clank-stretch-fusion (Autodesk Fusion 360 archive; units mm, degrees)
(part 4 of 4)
sketch "Sketch41" plane through (0, 0, 0) normal (0, 0, 1) x axis (1, 0, 0)
  line L1 (-93, -22.24) -> (-35, -22.24)
  line L2 (-93, 7.76) -> (-93, -22.24)
  line L3 (-35, 7.76) -> (-93, 7.76)
  line L4 (-35, -22.24) -> (-35, 7.76)
  line L5 (-17.5, 20.25) -> (-17.5, -22.74)
  line L6 (-93.5, -22.74) -> (-17.5, -22.74)
  line L7 (-93.5, 8.26) -> (-93.5, -22.74)
  line L8 (-17.5, 8.26) -> (-93.5, 8.26)
  line L9 (-36, -1.24) -> (-36, 6.76)
  line L10 (-62.3606, -1.24) -> (-36, -1.24)
  line L11 (-62.3606, -11.24) -> (-62.3606, -1.24)
  line L12 (-36, -11.24) -> (-62.3606, -11.24)
  line L13 (-36, -21.24) -> (-36, -11.24)
  line L14 (-65.6394, -21.24) -> (-36, -21.24)
  line L15 (-65.6394, -11.24) -> (-65.6394, -21.24)
  line L16 (-92, -11.24) -> (-65.6394, -11.24)
  line L17 (-92, 6.76) -> (-92, -11.24)
  line L18 (-36, 6.76) -> (-92, 6.76)
  line L19 (-20, -36.7914) -> (-20, -46.6952)
  line L20 (-45, 9.76) -> (-83, 9.76)
  line L21 (-45, 10.76) -> (-45, 9.76)
  line L22 (-83, 10.76) -> (-45, 10.76)
  line L23 (-83, 9.76) -> (-83, 10.76)
  line L24 (-64, 9.76) -> (-64, 7.76)
  circle C1 centre (-39, -6.24) radius 1.35
  circle C2 centre (-89, -18.24) radius 1.35
  point P10 (-64, 7.76)
  point P6 (-17.5, -22.74)
  point P11 (-17.5, -22.74)
  point P14 (-17.5, 8.26)
  point P18 (-62.3606, -11.24)
  point P16 (-36, -1.24)
  point P32 (-64, 7.76)
  point P33 (-64, 9.76)
  point P2 (-35, -22.24)
  point P3 (-93, -22.24)
  point P4 (-93, 7.76)
  point P8 (-39, -6.24)
  point P9 (-89, -18.24)
  point P1 (0, 0)
  point P5 (-35, 7.76)
  point P27 (0, 0)
  point P28 (-83, 9.76)
  point P29 (-45, 9.76)
  point P31 (-83, 10.76)
  horizontal L1
  vertical L2
  horizontal L3
  vertical L4
  equal C1 C2
  coincident L3 P10
  midpoint L3 P10
  coincident P6 P11
  perpendicular L5 L6
  perpendicular L6 L7
  coincident L5 P14
  perpendicular L5 L8
  vertical L9
  perpendicular L9 L10
  perpendicular L10 L11
  perpendicular L11 L12
  perpendicular L12 L13
  perpendicular L13 L14
  perpendicular L14 L15
  perpendicular L15 L16
  perpendicular L16 L17
  horizontal L18
  coincident P18 L16
  equal L12 L16
  coincident P16 L13
  vertical L19
  horizontal L20
  vertical L21
  horizontal L22
  vertical L23
  coincident P10 P32
  midpoint L20 P33
  vertical L24
  dimension "d2447" distance P2 P3 = 58
  dimension "d2448" distance P3 P4 = 30
  dimension "d2449" distance L4 P8 = 4
  dimension "d2450" distance L1 P9 = 4
  dimension "d2451" distance L2 P9 = 4
  dimension "d2452" distance L3 P8 = 14
  dimension "d2453" diameter C1 = 2.7
  dimension "d2454" distance P1 P10 = 64
  dimension "d2455" distance L1 P6 = 0.5
  dimension "d2456" distance P5 L8 = 0.5
  dimension "d2457" distance P4 L7 = 0.5
  dimension "d2458" distance L3 L18 = 1
  dimension "d2459" distance L4 L9 = 1
  dimension "d2460" distance L1 L14 = 1
  dimension "d2461" distance L2 L17 = 1
  dimension "d2462" distance P8 L12 = 5
  dimension "d2463" distance P8 L10 = 5 (= "d2462")
  dimension "d2479" distance L19 P27 = 20
  dimension "d2480" distance P10 L19 = 44
  dimension "d2481" distance P28 P29 = 38
  dimension "d2482" distance P28 P31 = 1
  dimension "d2483" distance P32 P33 = 2
extrude "Extrude174" sketch "Sketch41" profile of L5 C1 C2 L6 L7 L8 L9 L10 L11 L12 L13 L14 L15 L16 L17 L18 to an object
extrude "Extrude175" sketch "Sketch41" profile of L9 L10 L11 L12 L13 L14 L15 L16 L17 L18 to an object offset -5
fillet "Fillet71" radius 2
fillet "Fillet72" radius 4
component_from_bodies "Body->Comp1"
component_from_bodies "Body->Comp2"
component_from_bodies "Body->Comp3"
component_from_bodies "Body->Comp4"
component_from_bodies "Body->Comp5"
component_from_bodies "Body->Comp6"
component_from_bodies "Body->Comp7"
as_built_joint "As-built1"
as_built_joint "As-built2"
as_built_joint "As-built3"
as_built_joint "As-built4"
as_built_joint "As-built5"
as_built_joint "As-built6"
as_built_joint "As-built7"
component_insert "Component Insert111"
joint "Assemble127" alignAngle 0 alignOffsetX 0 alignOffsetY 0 alignOffsetZ 0
component_insert "Component Insert112"
joint "Assemble128" alignAngle 0 alignOffsetX 0 alignOffsetY 0 alignOffsetZ 0
component_insert "Component Insert113"
joint "Assemble129" alignAngle 180 alignOffsetX 0 alignOffsetY 0 alignOffsetZ 0
component_insert "Component Insert114"
joint "Assemble130" alignAngle 180 alignOffsetX 0 alignOffsetY 0 alignOffsetZ 0
component_insert "Component Insert115"
joint "Assemble131" alignAngle 0 alignOffsetX 0 alignOffsetY 0 alignOffsetZ 0
component_insert "Component Insert116"
joint "Assemble132" alignAngle 0 alignOffsetX 0 alignOffsetY 0 alignOffsetZ 0
component_insert "Component Insert117"
joint "Assemble133" alignAngle 180 alignOffsetX 0 alignOffsetY 0 alignOffsetZ 0
component_insert "Component Insert118"
joint "Assemble134" alignAngle 180 alignOffsetX 0 alignOffsetY 0 alignOffsetZ 0
component_insert "Component Insert119"
joint "Assemble135" alignAngle -90 alignOffsetX 0 alignOffsetY 0 alignOffsetZ 0
component_insert "Component Insert120"
joint "Assemble119" alignAngle 0 alignOffsetX 0 alignOffsetY 0 alignOffsetZ -2.1
component_insert "Component Insert128"
joint "Assemble136" alignAngle -90 alignOffsetX 0 alignOffsetY 0 alignOffsetZ 0
component_insert "Component Insert129"
joint "Assemble137" alignAngle -90 alignOffsetX 0 alignOffsetY 0 alignOffsetZ 0
component_insert "Component Insert130"
joint "Assemble138" alignAngle -90 alignOffsetX 0 alignOffsetY 0 alignOffsetZ 0
component_insert "Component Insert121"
joint "Assemble139" alignAngle -180 alignOffsetX 0 alignOffsetY 0 alignOffsetZ 0
component_insert "Component Insert131"
joint "Assemble140" alignAngle 0 alignOffsetX 0 alignOffsetY 0 alignOffsetZ 0
component_insert "Component Insert132"
joint "Assemble141" alignAngle 0 alignOffsetX 0 alignOffsetY 0 alignOffsetZ 0
component_insert "Component Insert133"
joint "Assemble142" alignAngle 180 alignOffsetX 0 alignOffsetY 0 alignOffsetZ 0
component_insert "Component Insert134"
joint "Assemble143" alignAngle 180 alignOffsetX 0 alignOffsetY 0 alignOffsetZ 0
component_insert "Component Insert135"
joint "Assemble144" alignAngle 180 alignOffsetX 0 alignOffsetY 0 alignOffsetZ 0
component_insert "Component Insert136"
joint "Assemble145" alignAngle 180 alignOffsetX 0 alignOffsetY 0 alignOffsetZ 0
component_insert "Component Insert137"
joint "Assemble146" alignAngle 0 alignOffsetX 0 alignOffsetY 0 alignOffsetZ 0
component_insert "Component Insert138"
joint "Assemble147" alignAngle 30 alignOffsetX 0 alignOffsetY 0 alignOffsetZ 0
component_insert "Component Insert139"
joint "Assemble148" alignAngle 0 alignOffsetX 0 alignOffsetY 0 alignOffsetZ 0
component_insert "Component Insert140"
joint "Assemble149" alignAngle 30 alignOffsetX 0 alignOffsetY 0 alignOffsetZ -1.5
component_insert "Component Insert141"
joint "Assemble150" alignAngle 30 alignOffsetX 0 alignOffsetY 0 alignOffsetZ -1.5
component_insert "Component Insert142"
joint "Assemble151" alignAngle 30 alignOffsetX 0 alignOffsetY 0 alignOffsetZ -1.5
component_insert "Component Insert143"
joint "Assemble152" alignAngle 30 alignOffsetX 0 alignOffsetY 0 alignOffsetZ -1.5
component_insert "Component Insert144"
joint "Assemble153" alignAngle 30 alignOffsetX 0 alignOffsetY 0 alignOffsetZ -1.5
component_insert "Component Insert145"
joint "Assemble154" alignAngle 30 alignOffsetX 0 alignOffsetY 0 alignOffsetZ -1.5
component_insert "Component Insert146"
joint "Assemble155" alignAngle 30 alignOffsetX 0 alignOffsetY 0 alignOffsetZ -1.5
component_insert "Component Insert147"
joint "Assemble156" alignAngle 30 alignOffsetX 0 alignOffsetY 0 alignOffsetZ 0
component_insert "Component Insert148"
joint "Assemble157" alignAngle 0 alignOffsetX 0 alignOffsetY 0 alignOffsetZ 0
component_insert "Component Insert149"
joint "Assemble158" alignAngle 0 alignOffsetX 0 alignOffsetY 0 alignOffsetZ 0
component_insert "Component Insert150"
joint "Assemble159" alignAngle 0 alignOffsetX 0 alignOffsetY 0 alignOffsetZ 0
component_insert "Component Insert151"
joint "Assemble160" alignAngle 0 alignOffsetX 0 alignOffsetY 0 alignOffsetZ 0
component_insert "Component Insert152"
joint "Assemble161" alignAngle 0 alignOffsetX 0 alignOffsetY 0 alignOffsetZ 0
component_insert "Component Insert153"
joint "Assemble162" alignAngle 0 alignOffsetX 0 alignOffsetY 0 alignOffsetZ 0
component_insert "Component Insert154"
joint "Assemble163" alignAngle 0 alignOffsetX 0 alignOffsetY 0 alignOffsetZ 0
component_insert "Component Insert155"
joint "Assemble164" alignAngle 0 alignOffsetX 0 alignOffsetY 0 alignOffsetZ 0
component_insert "Component Insert156"
joint "Assemble165" alignAngle 0 alignOffsetX 0 alignOffsetY 0 alignOffsetZ 0
component_insert "Component Insert157"
joint "Assemble166" alignAngle 0 alignOffsetX 0 alignOffsetY 0 alignOffsetZ 0
component_insert "Component Insert158"
joint "Assemble167" alignAngle 0 alignOffsetX 0 alignOffsetY 0 alignOffsetZ 0
component_insert "Component Insert159"
joint "Assemble168" alignAngle 0 alignOffsetX 0 alignOffsetY 0 alignOffsetZ 0
component_insert "Component Insert160"
joint "Assemble169" alignAngle 0 alignOffsetX 0 alignOffsetY 0 alignOffsetZ 0
component_insert "Component Insert161"
joint "Assemble170" alignAngle 0 alignOffsetX 0 alignOffsetY 0 alignOffsetZ 0
component_insert "Component Insert162"
joint "Assemble171" alignAngle 0 alignOffsetX 0 alignOffsetY 0 alignOffsetZ 0
component_insert "Component Insert163"
joint "Assemble172" alignAngle 0 alignOffsetX 0 alignOffsetY 0 alignOffsetZ 0
component_insert "Component Insert164"
joint "Assemble173" alignAngle 0 alignOffsetX 0 alignOffsetY 0 alignOffsetZ 0
component_insert "Component Insert165"
joint "Assemble174" alignAngle 0 alignOffsetX 0 alignOffsetY 0 alignOffsetZ 0
component_insert "Component Insert166"
joint "Assemble175" alignAngle 0 alignOffsetX 0 alignOffsetY 0 alignOffsetZ 0
component_insert "Component Insert167"
joint "Assemble176" alignAngle 0 alignOffsetX 0 alignOffsetY 0 alignOffsetZ 0
component_insert "Component Insert168"
joint "Assemble177" alignAngle 0 alignOffsetX 0 alignOffsetY 0 alignOffsetZ -6
component_insert "Component Insert169"
joint "Assemble178" alignAngle 0 alignOffsetX 0 alignOffsetY 0 alignOffsetZ 0
component_insert "Component Insert171"
joint "Assemble180" alignAngle 180 alignOffsetX 0 alignOffsetY 0 alignOffsetZ 0
component_insert "Component Insert172"
joint "Assemble181" alignAngle 0 alignOffsetX 0 alignOffsetY 0 alignOffsetZ 0
component_insert "Component Insert173"
joint "Assemble182" alignAngle 0 alignOffsetX 0 alignOffsetY 0 alignOffsetZ 0
component_insert "Component Insert174"
joint "Assemble183" alignAngle 0 alignOffsetX 0 alignOffsetY 0 alignOffsetZ 0
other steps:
base_feature "Base Feature1" bodies "YL Side Plate"
base_feature "Base Feature1" bodies "YL Belt Clip Teeth"
base_feature "Base Feature1" bodies "YL Belt Clip Face"
base_feature "Base Feature1" bodies "YL Top Plate"
base_feature "Base Feature1" bodies "YL Idler Cap"
base_feature "Base Feature1" bodies "YL Motor Plate"
base_feature "Base Feature1" bodies "YL Cable Clip"
create_component "CreateComponent1"
remove_body "RemoveBody1"
create_component "CreateComponent2"
remove_body "RemoveBody2"
create_component "CreateComponent3"
remove_body "RemoveBody3"
create_component "CreateComponent4"
remove_body "RemoveBody4"
create_component "CreateComponent5"
remove_body "RemoveBody5"
create_component "CreateComponent6"
remove_body "RemoveBody6"
create_component "CreateComponent7"
remove_body "RemoveBody7"
joint_origin "JointOrigin2"
joint_origin "JointOrigin3"
joint_origin "JointOrigin1"
joint_origin "JointOrigin2"
joint_origin "JointOrigin1"
joint_origin "JointOrigin2"
joint_origin "JointOrigin3"
joint_origin "JointOrigin4"
joint_origin "JointOrigin1"
joint_origin "JointOrigin3"
joint_origin "JointOrigin5"
joint_origin "JointOrigin6"
joint_origin "JointOrigin7"
joint_origin "JointOrigin8"
joint_origin "JointOrigin9"
joint_origin "JointOrigin1"
joint_origin "JointOrigin2"
joint_origin "JointOrigin1"
joint_origin "JointOrigin5"
joint_origin "JointOrigin6"
joint_origin "JointOrigin7"
joint_origin "JointOrigin8"
joint_origin "JointOrigin9"
joint_origin "JointOrigin10"
joint_origin "JointOrigin11"
joint_origin "JointOrigin12"
joint_origin "JointOrigin2"
joint_origin "JointOrigin3"
joint_origin "JointOrigin4"
joint_origin "JointOrigin5"
joint_origin "JointOrigin2"
joint_origin "JointOrigin3"
joint_origin "JointOrigin4"
joint_origin "JointOrigin5"
joint_origin "JointOrigin6"
joint_origin "JointOrigin4"
joint_origin "JointOrigin5"
joint_origin "JointOrigin6"
joint_origin "JointOrigin7"
joint_origin "JointOrigin8"
joint_origin "JointOrigin9"
joint_origin "JointOrigin2"
joint_origin "JointOrigin3"
joint_origin "JointOrigin13"
joint_origin "JointOrigin14"
joint_origin "JointOrigin15"
joint_origin "JointOrigin10"
named bodies: "YL Side Plate", "YL Belt Clip Teeth", "YL Belt Clip Face", "YL Idler Cap", "YL Motor Plate", "YL Top Plate", "YL Cable Clip"

design "HW_M5 Nylock"
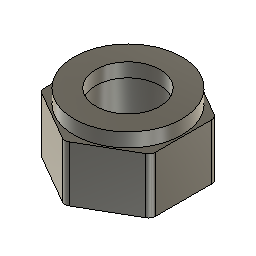
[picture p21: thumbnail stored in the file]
sketch "Sketch1" plane through (0, 0, 0) normal (0, 0, 1) x axis (1, 0, 0)
  line L1 (0, 4.6188) -> (4, 2.3094)
  line L2 (-4, 2.3094) -> (0, 4.6188)
  line L3 (-4, -2.3094) -> (-4, 2.3094)
  line L4 (0, -4.6188) -> (-4, -2.3094)
  line L5 (4, -2.3094) -> (0, -4.6188)
  line L6 (4, 2.3094) -> (4, -2.3094)
  circle C1 centre (0, 0) radius 2.55
  circle C2 centre (0, 0) radius 3.875
  circle C3 centre (0, 0) radius 2.3
  point P1 (0, 0)
  point P8 (0, 0)
  point P9 (0, 0)
  point P4 (-4, 2.3094)
  coincident P1 P8
  vertical L6
  coincident P8 P9
  concentric C1 C2
  concentric C1 C3
  dimension "d1" distance P4 L6 = 8
  dimension "d2" diameter C1 = 5.1
  dimension "d5" diameter C2 = 7.75
  dimension "d9" distance C1 C3 = 0.25
extrude "Extrude1" new body sketch "Sketch1" profile of L1 L2 L3 L4 L5 L6 C1 along normal blind 4
extrude "Extrude2" sketch "Sketch1" profile of C1 C2 C3 blind 1
fillet "Fillet1" radius 0.5

design "HW_M4x25-SHCS"
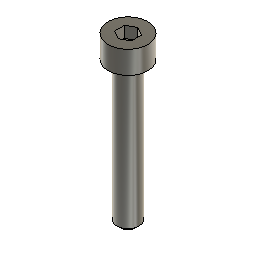
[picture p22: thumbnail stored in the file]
sketch "Sketch1" plane through (0, 0, 0) normal (0, 1, 0) x axis (1, 0, 0)
  line L1 (0, 25) -> (0, -4)
  line L2 (1.45, 25) -> (0, 25)
  line L3 (1.95, 24.5) -> (1.45, 25)
  line L4 (1.95, 0) -> (1.95, 24.5)
  line L5 (3.5, 0) -> (1.95, 0)
  line L6 (3.5, -4) -> (3.5, 0)
  line L7 (0, -4) -> (3.5, -4)
  point P1 (0, 0)
  point P4 (1.45, 25)
  point P5 (1.95, 24.5)
  point P3 (0, 25)
  point P7 (3.5, 0)
  point P8 (3.5, -4)
  point P2 (0, -4)
  vertical L1
  perpendicular L1 L2
  perpendicular L2 L4
  perpendicular L4 L5
  perpendicular L5 L6
  horizontal L7
  coincident P1 L1
  coincident P1 L5
  dimension "d1" distance P1 L2 = 25
  dimension "d2" angle L2 L3 = 45
  dimension "d3" distance P4 P5 = 0.5
  dimension "d4" distance P3 L4 = 1.95 (= "( 3.9 / 2 ) * 1 mm")
  dimension "d5" distance P7 P8 = 4
  dimension "d6" distance P2 P8 = 3.5 (= "( 7 / 2 ) * 1 mm")
revolve "Revolve1" sketch "Sketch1" AlongAngle 360
sketch "Sketch2" plane through (0, 0, 4) normal (0, 0, 1) x axis (-1, 0, 0)
  line L1 (0, -1.7321) -> (-1.5, -0.866)
  line L2 (1.5, -0.866) -> (0, -1.7321)
  line L3 (1.5, 0.866) -> (1.5, -0.866)
  line L4 (0, 1.7321) -> (1.5, 0.866)
  line L5 (-1.5, 0.866) -> (0, 1.7321)
  line L6 (-1.5, -0.866) -> (-1.5, 0.866)
  circle C1 centre (0, 0) radius 3.5
  point P1 (0, 0)
  point P9 (0, 0)
  point P5 (1.5, -0.866)
  coincident P1 P9
  vertical L6
  dimension "d8" distance P5 L6 = 3
extrude "Extrude1" cut sketch "Sketch2" profile of L1 L2 L3 L4 L5 L6 against normal blind 2

design "PP_BRNG_6806-30x42x7"
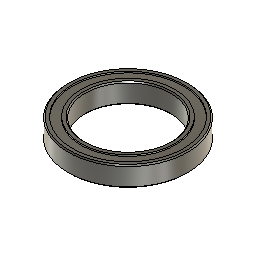
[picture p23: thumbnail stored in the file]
sketch "Sketch1" plane through (0, 0, 0) normal (0, 1, 0) x axis (1, 0, 0)
  line L1 (16.5, -3.5) -> (15, -3.5)
  line L2 (15, 3.5) -> (16.5, 3.5)
  line L3 (15, -3.5) -> (15, 3.5)
  line L4 (21, -3.5) -> (19.5, -3.5)
  line L5 (21, 3.5) -> (21, -3.5)
  line L6 (19.5, 3.5) -> (21, 3.5)
  line L7 (19.5, -3) -> (16.5, -3)
  line L8 (19.5, 3) -> (16.5, 3)
  line L9 (16.5, -3) -> (16.5, -3.5)
  line L10 (16.5, 3.5) -> (16.5, 3)
  line L11 (19.5, 3) -> (19.5, 3.5)
  line L12 (19.5, -3.5) -> (19.5, -3)
  line L13 (0, 0) -> (21, 0)
  point P11 (19.5, -3)
  point P12 (16.5, 3)
  point P14 (21, 0)
  point P1 (0, 0)
  point P15 (0, 0)
  point P16 (15, 0)
  point P6 (19.5, -3.5)
  point P2 (15, -3.5)
  point P3 (16.5, -3.5)
  point P10 (16.5, -3)
  point P7 (21, -3.5)
  point P8 (21, 3.5)
  horizontal L1
  vertical L9
  horizontal L2
  vertical L3
  horizontal L4
  vertical L5
  horizontal L6
  vertical L11
  coincident P11 L11
  perpendicular L7 L11
  coincident P12 L9
  perpendicular L8 L9
  collinear L9 L10
  collinear L11 L12
  midpoint L5 P14
  coincident P1 P15
  horizontal L13
  midpoint L3 P16
  coincident L13 P16
  equal L1 L4
  equal L9 L10
  coincident L1 P6
  dimension "d1" distance P1 L3 = 15 (= "( 30 / 2 ) * 1 mm")
  dimension "d2" distance P1 L5 = 21 (= "( 42 / 2 ) * 1 mm")
  dimension "d3" distance P2 P3 = 1.5
  dimension "d4" distance P3 P10 = 0.5
  dimension "d5" distance P7 P8 = 7
revolve "Revolve1" sketch "Sketch1" AlongAngle 360
chamfer "Chamfer1" distance 0.4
